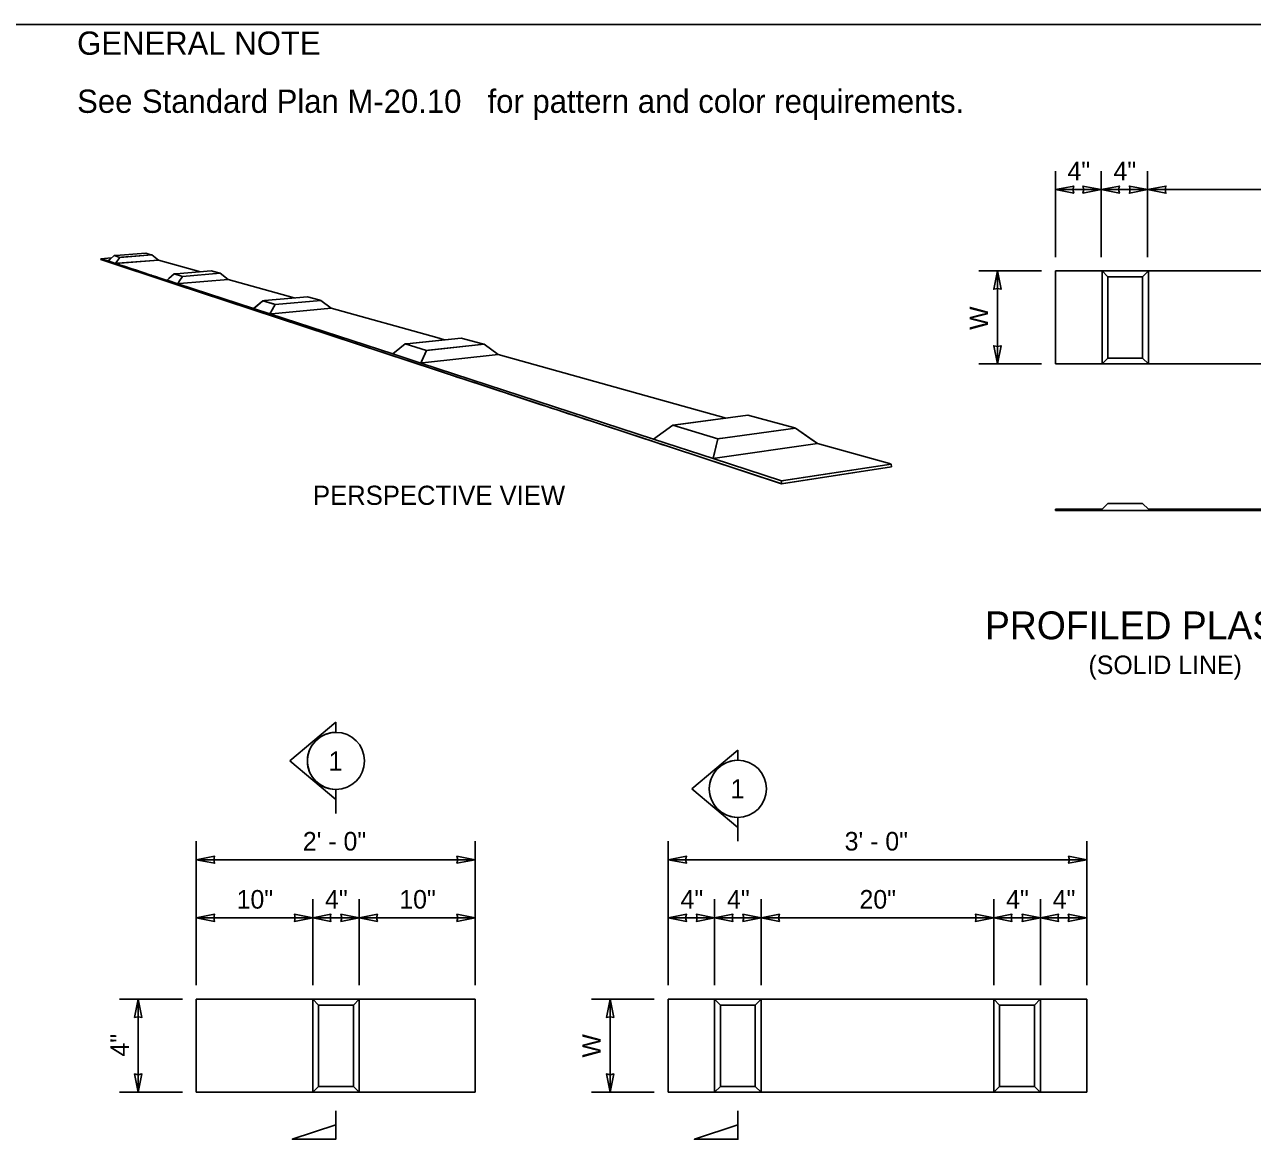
# Model space of a CAD drawing. Extents: x 99862 to 104211, y 98939 to 102078.
# Drawn here: x 101193 to 102250, y 101106 to 102076 of the extents above; entities that cross this region are included whole.
import ezdxf

# ---------------------------------------------------------------- set-up
doc = ezdxf.new("R2010")
doc.units = 0
for name, color, linetype in [('Level 1', 7, 'Continuous'), ('Level 15', 7, 'Continuous'), ('Level 16', 7, 'Continuous'), ('Level 2', 7, 'Continuous'), ('Level 20', 7, 'Continuous'), ('Level 9', 7, 'Continuous')]:
    doc.layers.add(name, color=color, linetype=linetype)

msp = doc.modelspace()

# ---------------------------------------------------------------- linework, layer by layer
at = {"layer": 'Level 1'}
msp.add_lwpolyline([(99862, 99999.5), (103151, 99999.5), (103151, 102075.5), (99862, 102075.5)], close=True, dxfattribs=at)
at = {"layer": 'Level 15'}
for p, q in [((102080.6, 101875.4), (102080.6, 101949.4)), ((102119.9, 101875.4), (102119.9, 101949.4)), ((102159.9, 101875.4), (102159.9, 101949.4)), ((102119.9, 101933.4), (102080.6, 101933.4)), ((102159.9, 101933.4), (102119.9, 101933.4)), ((102389.9, 101933.4), (102159.9, 101933.4)), ((102068.6, 101863.4), (102014.6, 101863.4)), ((102030.6, 101783.4), (102030.6, 101863.4)), ((102068.6, 101783.4), (102014.6, 101783.4)), ((101341.1, 101248.6), (101341.1, 101372.6)), ((101581.1, 101248.6), (101581.1, 101372.6)), ((101747.2, 101248.6), (101747.2, 101372.6)), ((102107.5, 101248.6), (102107.5, 101372.6)), ((101581.1, 101356.6), (101341.1, 101356.6)), ((102107.5, 101356.6), (101747.2, 101356.6)), ((101441.3, 101248.6), (101441.3, 101322.6)), ((101481.3, 101248.6), (101481.3, 101322.6)), ((101787.2, 101248.6), (101787.2, 101322.6)), ((101827.2, 101248.6), (101827.2, 101322.6)), ((102027.4, 101248.6), (102027.4, 101322.6)), ((102067.6, 101248.6), (102067.6, 101322.6)), ((101441.3, 101306.6), (101341.1, 101306.6)), ((101481.3, 101306.6), (101441.3, 101306.6)), ((101581.1, 101306.6), (101481.3, 101306.6)), ((101787.2, 101306.6), (101747.2, 101306.6)), ((101827.2, 101306.6), (101787.2, 101306.6)), ((102027.4, 101306.6), (101827.2, 101306.6)), ((102067.6, 101306.6), (102027.4, 101306.6)), ((102107.5, 101306.6), (102067.6, 101306.6)), ((101329.1, 101236.6), (101275.1, 101236.6)), ((101291.1, 101156.6), (101291.1, 101236.6)), ((101735.2, 101236.6), (101681.2, 101236.6)), ((101697.2, 101156.6), (101697.2, 101236.6)), ((101329.1, 101156.6), (101275.1, 101156.6)), ((101735.2, 101156.6), (101681.2, 101156.6))]:
    msp.add_line(p, q, dxfattribs=at)
for points in [[(102080.6, 101933.4), (102096.3, 101930.3), (102095.6, 101933.4), (102096.3, 101936.5)], [(102119.9, 101933.4), (102104.2, 101936.5), (102104.9, 101933.4), (102104.2, 101930.3)], [(102119.9, 101933.4), (102135.6, 101930.3), (102134.9, 101933.4), (102135.6, 101936.5)], [(102159.9, 101933.4), (102144.2, 101936.5), (102144.9, 101933.4), (102144.2, 101930.3)], [(102159.9, 101933.4), (102175.6, 101930.3), (102174.9, 101933.4), (102175.6, 101936.5)], [(102030.6, 101863.4), (102027.5, 101847.7), (102030.6, 101848.4), (102033.7, 101847.7)], [(102030.6, 101783.4), (102033.7, 101799.1), (102030.6, 101798.4), (102027.5, 101799.1)], [(101341.1, 101356.6), (101356.8, 101353.6), (101356.1, 101356.6), (101356.8, 101359.7)], [(101581.1, 101356.6), (101565.4, 101359.7), (101566.1, 101356.6), (101565.4, 101353.6)], [(101747.2, 101356.6), (101763, 101353.6), (101762.2, 101356.6), (101763, 101359.7)], [(102107.5, 101356.6), (102091.8, 101359.7), (102092.6, 101356.6), (102091.8, 101353.6)], [(101341.1, 101306.6), (101356.8, 101303.6), (101356.1, 101306.6), (101356.8, 101309.7)], [(101441.3, 101306.6), (101425.5, 101309.7), (101426.3, 101306.6), (101425.5, 101303.6)], [(101441.3, 101306.6), (101457, 101303.6), (101456.3, 101306.6), (101457, 101309.7)], [(101481.3, 101306.6), (101465.5, 101309.7), (101466.3, 101306.6), (101465.5, 101303.6)], [(101481.3, 101306.6), (101497, 101303.6), (101496.3, 101306.6), (101497, 101309.7)], [(101581.1, 101306.6), (101565.4, 101309.7), (101566.1, 101306.6), (101565.4, 101303.6)], [(101747.2, 101306.6), (101763, 101303.6), (101762.2, 101306.6), (101763, 101309.7)], [(101787.2, 101306.6), (101771.5, 101309.7), (101772.2, 101306.6), (101771.5, 101303.6)], [(101787.2, 101306.6), (101803, 101303.6), (101802.2, 101306.6), (101803, 101309.7)], [(101827.2, 101306.6), (101811.5, 101309.7), (101812.2, 101306.6), (101811.5, 101303.6)], [(101827.2, 101306.6), (101843, 101303.6), (101842.2, 101306.6), (101843, 101309.7)], [(102027.4, 101306.6), (102011.6, 101309.7), (102012.4, 101306.6), (102011.6, 101303.6)], [(102027.4, 101306.6), (102043.1, 101303.6), (102042.4, 101306.6), (102043.1, 101309.7)], [(102067.6, 101306.6), (102051.8, 101309.7), (102052.6, 101306.6), (102051.8, 101303.6)], [(102067.6, 101306.6), (102083.3, 101303.6), (102082.6, 101306.6), (102083.3, 101309.7)], [(102107.4, 101306.6), (102091.6, 101309.7), (102092.4, 101306.6), (102091.6, 101303.6)], [(101291.1, 101236.6), (101288, 101220.9), (101291.1, 101221.6), (101294.2, 101220.9)], [(101697.2, 101236.6), (101694.1, 101220.9), (101697.2, 101221.6), (101700.3, 101220.9)], [(101291.1, 101156.6), (101294.2, 101172.4), (101291.1, 101171.6), (101288, 101172.4)], [(101697.2, 101156.6), (101700.3, 101172.4), (101697.2, 101171.6), (101694.1, 101172.4)]]:
    msp.add_lwpolyline(points, close=True, dxfattribs=at)
at = {"layer": 'Level 16'}
for points in [[(101297.5, 101878.7), (101271.9, 101876.7), (101270.3, 101876.6)], [(101299.3, 101878.2), (101297.5, 101878.7)], [(101297.5, 101878.7), (101301.1, 101877.7), (101302.9, 101877.2)], [(101268.1, 101874.7), (101258.9, 101874)], [(101258.9, 101874), (101265.1, 101872)], [(101258.9, 101874), (101259, 101873.2)], [(101259, 101873.2), (101322.8, 101852.2), (101388.3, 101830.6), (101843.2, 101680.7), (101844.8, 101680.2)], [(101317.9, 101853.8), (101259, 101873.2)], [(101265.1, 101872), (101266.8, 101873.5), (101270.3, 101876.6)], [(101266.7, 101871.4), (101265.1, 101872)], [(101265.1, 101872), (101271.6, 101869.9)], [(101266.7, 101871.4), (101265.1, 101872)], [(101270.3, 101876.6), (101275.2, 101875.1)], [(101271.6, 101869.9), (101272.8, 101871.6), (101275.2, 101875.1)], [(101308.6, 101872.7), (101271.6, 101869.9)], [(101271.6, 101869.9), (101314.2, 101855.9), (101315.9, 101855.4)], [(101297.8, 101861.3), (101294.5, 101862.4), (101289.6, 101864), (101284.7, 101865.6), (101279.8, 101867.2), (101274.9, 101868.8), (101271.6, 101869.9)], [(101308.6, 101872.7), (101273.3, 101870)], [(101275.2, 101875.1), (101302.9, 101877.2)], [(101302.9, 101877.2), (101288.2, 101876.1), (101276.8, 101875.2), (101275.2, 101875.1)], [(101308.6, 101872.7), (101302.9, 101877.2)], [(101308.6, 101872.7), (101344.7, 101862.7)], [(101302.7, 101859.7), (101301.1, 101860.2)], [(101307.7, 101858.1), (101306, 101858.6)], [(101315.9, 101855.4), (101317.4, 101856.8), (101322.1, 101860.9)], [(101322.1, 101860.9), (101323.8, 101861), (101354, 101863.5)], [(101322.1, 101860.9), (101329.1, 101858.7)], [(101325.1, 101852.4), (101326.1, 101854), (101329.1, 101858.7)], [(101361.6, 101861.4), (101329.1, 101858.7)], [(101357.1, 101862.7), (101354, 101863.5)], [(101354, 101863.5), (101361.6, 101861.4)], [(101368.6, 101856.1), (101361.6, 101861.4)], [(101312.6, 101856.5), (101310.9, 101857)], [(101315.9, 101855.4), (101325.1, 101852.4)], [(101368.6, 101856.1), (101326.7, 101852.5), (101325.1, 101852.4)], [(101368.6, 101856.1), (101326.7, 101852.5), (101325.1, 101852.4)], [(101325.1, 101852.4), (101390.3, 101831.1)], [(101368.6, 101856.1), (101425.4, 101840.2)], [(101357.7, 101841.7), (101356, 101842.3)], [(101362.1, 101839.2), (101360.4, 101839.8)], [(101367, 101837.6), (101365.3, 101838.1)], [(101371.9, 101836), (101370.3, 101836.5)], [(101390.3, 101831.1), (101391.9, 101832.4), (101398.2, 101837.8)], [(101398.2, 101837.8), (101390.3, 101831.1)], [(101436.7, 101841.3), (101399.8, 101837.9), (101398.2, 101837.8)], [(101398.2, 101837.8), (101407.4, 101835), (101408.9, 101834.5)], [(101408.9, 101834.5), (101398.2, 101837.8)], [(101408.9, 101834.5), (101448.3, 101838.1)], [(101436.7, 101841.3), (101446.6, 101838.6), (101448.3, 101838.1)], [(101448.3, 101838.1), (101457.1, 101831.4)], [(101376.8, 101834.4), (101375.2, 101834.9)], [(101381.7, 101832.8), (101380.1, 101833.3)], [(101390.3, 101831.1), (101404.4, 101826.5)], [(101393.2, 101829), (101391.5, 101829.5)], [(101844.8, 101680.2), (101746.6, 101712.5), (101741.7, 101714.1), (101736.8, 101715.8), (101731.9, 101717.4), (101727, 101719), (101722.1, 101720.6), (101681.2, 101734.1), (101676.3, 101735.7), (101671.4, 101737.3), (101666.5, 101738.9), (101661.5, 101740.6), (101656.6, 101742.2), (101651.7, 101743.8), (101646.8, 101745.4), (101641.9, 101747), (101637, 101748.6), (101581.4, 101767), (101576.4, 101768.6), (101571.5, 101770.2), (101566.6, 101771.8), (101561.7, 101773.4), (101556.8, 101775.1), (101396.4, 101827.9)], [(101404.4, 101826.5), (101405.3, 101828.1), (101408.9, 101834.5)], [(101457.1, 101831.4), (101406, 101826.6), (101404.4, 101826.5)], [(101457.1, 101831.4), (101406, 101826.6), (101404.4, 101826.5)], [(101404.4, 101826.5), (101510.1, 101792)], [(101457.1, 101831.4), (101548.2, 101806.1), (101554.7, 101804.2)], [(101520.7, 101800.6), (101522.4, 101800.8), (101569.1, 101805.6)], [(101569.1, 101805.6), (101527.4, 101801.3)], [(101569.1, 101805.6), (101587.3, 101800.8), (101588.9, 101800.3)], [(101510.1, 101792), (101511.6, 101793.2), (101520.7, 101800.6)], [(101520.7, 101800.6), (101510.1, 101792)], [(101520.7, 101800.6), (101539.1, 101795)], [(101534.3, 101784.1), (101539.1, 101795)], [(101539.1, 101795), (101535, 101785.6), (101534.3, 101784.1)], [(101539.1, 101795), (101588.9, 101800.3)], [(101588.9, 101800.3), (101540.8, 101795.2), (101539.1, 101795)], [(101601, 101791.4), (101588.9, 101800.3)], [(101510.1, 101792), (101534.3, 101784.1)], [(101601, 101791.4), (101535.9, 101784.3), (101534.3, 101784.1)], [(101601, 101791.4), (101535.9, 101784.3), (101534.3, 101784.1)], [(101534.3, 101784.1), (101734.7, 101718.7)], [(101601, 101791.4), (101797, 101736.8)], [(101734.7, 101718.7), (101751.1, 101730.7)], [(101751.1, 101730.7), (101815.7, 101739.3)], [(101751.1, 101730.7), (101789.9, 101718.9)], [(101815.7, 101739.3), (101756, 101731.3)], [(101815.7, 101739.3), (101855.2, 101728.7), (101856.9, 101728.2)], [(101789.9, 101718.9), (101856.9, 101728.2)], [(101856.9, 101728.2), (101796.4, 101719.9), (101791.5, 101719.2), (101789.9, 101718.9)], [(101875.7, 101714.9), (101856.9, 101728.2)], [(101856.9, 101728.2), (101872.3, 101717.3)], [(101734.7, 101718.7), (101785.9, 101701.9)], [(101785.9, 101701.9), (101789.9, 101718.9)], [(101789.9, 101718.9), (101786.3, 101703.5), (101785.9, 101701.9)], [(101875.7, 101714.9), (101787.6, 101702.2), (101785.9, 101701.9)], [(101875.7, 101714.9), (101787.6, 101702.2), (101785.9, 101701.9)], [(101875.7, 101714.9), (101937.6, 101697.7), (101939.2, 101697.2)], [(101844.7, 101682.7), (101785.9, 101701.9)], [(101844.7, 101682.7), (101939.2, 101697.2)], [(101939.2, 101697.2), (101846.4, 101683), (101844.7, 101682.7)], [(101844.8, 101680.2), (101939.3, 101694.7)], [(101939.3, 101694.7), (101846.5, 101680.4), (101844.8, 101680.2)], [(101939.3, 101694.7), (101939.2, 101697.2)], [(101844.8, 101680.2), (101844.7, 101682.7)]]:
    msp.add_lwpolyline(points, dxfattribs=at)
at = {"layer": 'Level 2'}
for p, q in [((102080.6, 101863.4), (102080.6, 101783.4)), ((102080.6, 101863.4), (103089.3, 101863.4)), ((102120.6, 101863.4), (102120.6, 101783.4)), ((102125.6, 101858.4), (102120.6, 101863.4)), ((102125.6, 101858.4), (102155.6, 101858.4)), ((102125.6, 101858.4), (102125.6, 101788.4)), ((102155.6, 101858.4), (102160.6, 101863.4)), ((102155.6, 101858.4), (102155.6, 101788.4)), ((102160.6, 101863.4), (102160.6, 101783.4)), ((102080.6, 101783.4), (103089.3, 101783.4)), ((102125.6, 101788.4), (102120.6, 101783.4)), ((102125.6, 101788.4), (102155.6, 101788.4)), ((102155.6, 101788.4), (102160.6, 101783.4)), ((102080.6, 101658.4), (102120.6, 101658.4)), ((102080.6, 101658.4), (102080.6, 101657.4)), ((102080.6, 101657.4), (103088.2, 101657.4)), ((102120.6, 101658.4), (102125.6, 101663.4)), ((102125.6, 101663.4), (102155.6, 101663.4)), ((102155.6, 101663.4), (102160.6, 101658.4)), ((102160.6, 101658.4), (102390.6, 101658.4)), ((101341.1, 101236.6), (101581.1, 101236.6)), ((101341.1, 101236.6), (101341.1, 101156.6)), ((101441.3, 101236.6), (101441.3, 101156.6)), ((101446.3, 101231.6), (101441.3, 101236.6)), ((101476.3, 101231.6), (101481.3, 101236.6)), ((101481.3, 101236.6), (101481.3, 101156.6)), ((101581.1, 101236.6), (101581.1, 101156.6)), ((101747.2, 101236.6), (102107.5, 101236.6)), ((101747.2, 101236.6), (101747.2, 101156.6)), ((101787.2, 101236.6), (101787.2, 101156.6)), ((101792.2, 101231.6), (101787.2, 101236.6)), ((101822.2, 101231.6), (101827.2, 101236.6)), ((101827.2, 101236.6), (101827.2, 101156.6)), ((102027.4, 101236.6), (102027.4, 101156.6)), ((102032.4, 101231.6), (102027.4, 101236.6)), ((102062.4, 101231.6), (102067.4, 101236.6)), ((102067.6, 101236.6), (102067.6, 101156.6)), ((102107.5, 101156.6), (102107.5, 101236.6)), ((101446.3, 101231.6), (101476.3, 101231.6)), ((101446.3, 101231.6), (101446.3, 101161.6)), ((101476.3, 101231.6), (101476.3, 101161.6)), ((101792.2, 101231.6), (101792.2, 101161.6)), ((101792.2, 101231.6), (101822.2, 101231.6)), ((101822.2, 101231.6), (101822.2, 101161.6)), ((102032.4, 101231.6), (102062.4, 101231.6)), ((102032.4, 101231.6), (102032.4, 101161.6)), ((102062.4, 101231.6), (102062.4, 101161.6)), ((101446.3, 101161.6), (101441.3, 101156.6)), ((101446.3, 101161.6), (101476.3, 101161.6)), ((101476.3, 101161.6), (101481.3, 101156.6)), ((101792.2, 101161.6), (101787.2, 101156.6)), ((101792.2, 101161.6), (101822.2, 101161.6)), ((101822.2, 101161.6), (101827.2, 101156.6)), ((102032.4, 101161.6), (102027.4, 101156.6)), ((102032.4, 101161.6), (102062.4, 101161.6)), ((102062.4, 101161.6), (102067.4, 101156.6)), ((101341.1, 101156.6), (101581.1, 101156.6)), ((101747.2, 101156.6), (102107.5, 101156.6))]:
    msp.add_line(p, q, dxfattribs=at)
at = {"layer": 'Level 20'}
msp.add_line((101441.3, 101236.6), (101441.3, 101236.6), dxfattribs=at)
msp.add_line((101441.3, 101236.6), (101441.3, 101236.6), dxfattribs=at)
at = {"layer": 'Level 9'}
for p, q in [((101461.3, 101475), (101421.5, 101441.7)), ((101461.3, 101466.3), (101461.3, 101475)), ((101807.2, 101451), (101767.5, 101417.7)), ((101807.2, 101442.3), (101807.2, 101451)), ((101421.5, 101441.7), (101461.3, 101408.4)), ((101461.3, 101408.4), (101461.3, 101417.1)), ((101461.3, 101417.1), (101461.3, 101396.6)), ((101767.5, 101417.7), (101807.2, 101384.4)), ((101807.2, 101384.4), (101807.2, 101393.1)), ((101807.2, 101393.1), (101807.2, 101372.6)), ((101461.1, 101140.6), (101461.1, 101116.1)), ((101807.2, 101140.6), (101807.2, 101116.1))]:
    msp.add_line(p, q, dxfattribs=at)
for points in [[(101461.1, 101128.5), (101423.7, 101116.1), (101461.1, 101116.1)], [(101807.2, 101128.5), (101769.8, 101116.1), (101807.2, 101116.1)]]:
    msp.add_lwpolyline(points, close=True, dxfattribs=at)
for centre in [(101461.3, 101441.7), (101807.2, 101417.7)]:
    msp.add_circle(centre, 24.6, dxfattribs=at)
for centre in [(101461.3, 101441.7), (101807.2, 101417.7)]:
    msp.add_arc(centre, 24.6, 89.9978, 270.0022, dxfattribs=at)

# ---------------------------------------------------------------- texts
at = {"layer": 'Level 20'}
for s, height, p in [('GENERAL NOTE', 20, (101238.5, 102049.5)), ('See', 20, (101238.5, 101999.5)), (' Standard Plan M-20.10', 20, (101286.8, 101999.5)), (' for pattern and color requirements.', 20, (101584.3, 101999.5)), ('4"', 16, (102090.9, 101941.4)), ('4"', 16, (102130.5, 101941.4)), ('PERSPECTIVE VIEW', 16.5, (101441.5, 101662.1)), ('PROFILED PLASTIC', 24, (102019.9, 101546.4)), ('(SOLID LINE)', 16, (102109, 101516.4)), ('1', 16.5, (101454.8, 101433.4)), ('1', 16.5, (101800.8, 101409.4)), ('2\' - 0"', 16, (101432.8, 101364.6)), ('3\' - 0"', 16, (101899.1, 101364.6)), ('10"', 16, (101375.8, 101314.6)), ('4"', 16, (101451.9, 101314.6)), ('10"', 16, (101515.8, 101314.6)), ('4"', 16, (101757.9, 101314.6)), ('4"', 16, (101797.9, 101314.6)), ('20"', 16, (101911.9, 101314.6)), ('4"', 16, (102038.1, 101314.6)), ('4"', 16, (102078.2, 101314.6))]:
    msp.add_text(s, height=height, dxfattribs=at).set_placement(p)
for s, p in [('W', (102022.6, 101812.7)), ('4"', (101283.1, 101187.3)), ('W', (101689.2, 101186.4))]:
    msp.add_text(s, height=16, rotation=90, dxfattribs=at).set_placement(p)

doc.saveas('drawing.dxf')
